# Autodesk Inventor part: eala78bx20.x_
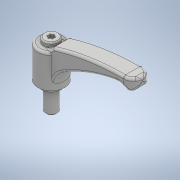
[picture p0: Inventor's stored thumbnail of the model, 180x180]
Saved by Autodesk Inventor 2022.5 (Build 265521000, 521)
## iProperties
Created: 2018-05
Part Number: eala78bx20.x_
Material: 一般
Document SubType Name: Modeling
Designer: imaocorp
Density: 1 g/cm^3
Appearance: 既定
Sending System: SOLIDWORKS 2016-2016286
MC: AMD64
MC_MODEL: AMD64 Family 21 Model 2 Stepping 0, AuthenticAMD
OS: Windows_NT
FRU: Parasolid Version 28.0, build 224,  7-29-2016
FORMAT: text
GUISE: transmit
KEY: eala78bx20
FILE: eala78bx20.x_t
DATE: Fri May 18 11:31:50 2018
Author: imaocorp
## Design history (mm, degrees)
feature "Base1"
node "ソリッド1"
